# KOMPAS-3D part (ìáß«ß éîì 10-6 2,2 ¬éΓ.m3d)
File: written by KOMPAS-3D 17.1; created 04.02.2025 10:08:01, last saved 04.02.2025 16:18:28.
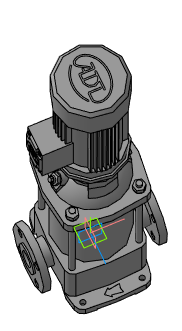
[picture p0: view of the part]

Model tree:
1. Операция без истории:2  (labels: Насос ВМН 10-6 2,2 кВт)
